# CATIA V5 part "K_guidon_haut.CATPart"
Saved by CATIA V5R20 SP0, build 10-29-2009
Part number: guidon_haut
Publications: "Diametre_guidon_haut", "Longueur_support_poignet"
Bounding box of the stored display mesh (mm): x -250 to 250, y -37.5 to 37.5, z 220 to 707.466
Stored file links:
  G:\Khaled_CFAO_2011\SIL\SIL_GR2\ahabrial\ahabrial\Khaled\CAD_ThinkMOTION\K_guidon_haut.CATPart
  G:\Données\Ecole\IFMA\2A\Thinkmotion2\Etape18\trotinette.CATProduct
  G:\Khaled_CFAO_2011\SIL\SIL_GR2\ahabrial\ahabrial\Etape18\skl_guidon_haut.CATPart
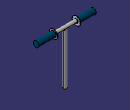
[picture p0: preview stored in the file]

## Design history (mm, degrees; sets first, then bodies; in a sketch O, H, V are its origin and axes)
Parameters
  Diametre_guidon_haut = 30 mm
  Longueur_support_poignet = 500 mm
  Longueur_poignet = 150 mm
  Diametre_poignet = 50 mm
External parameters (linked from other documents)
  External.Longueur_guidon = 300 mm
Set1
  Plane1 "Plan_guidon_haut_poignet": linked copy from another document
  Point1: linked copy from another document
  Plane2 "Plan_ref": linked copy from another document
Body1 (main body)
  Sketch1 on Plane1, origin (0, 0, 670), H (1, 0, 0), V (0, -1, 0)
    circle A1 centre (0, 0) radius 15
    point P1 (0, 0)
    reference projected point E1 (0, 0) from Point1
    radius A1 = 15 {= Diametre_guidon_haut /2}
    coincidence: P1 H, P1 E1
  Pad1: profile Sketch1, direction (0, 0, -1), length 450 {= External.Longueur_guidon *1.5}
  Sketch2 on Plane2, origin (0, 0, 0), H (0, 1, 0), V (0, 0, 1)
    circle A1 centre (0, 670) radius 15
    point P1 (0, 670)
    reference projected point E1 (0, 670) from Point1
    radius A1 = 15 {= Diametre_guidon_haut /2}
    coincidence: P1 E1
  Pad2: profile Sketch2, direction (1, 0, 0), length 250 {= Longueur_support_poignet/2}, mirrored extent
  Sketch3 on end face of Pad2, origin (250, 0, 0), H (0, 1, 0), V (0, 0, 1)
    circle A1 centre (0, 670) radius 25
    point P1 (0, 670)
    reference projected point E1 (0, 670) from Point1
    radius A1 = 25 {= Diametre_poignet /2}
    coincidence: E1 P1
  Pad3: profile Sketch3, direction (-1, 0, 0), length 150 {= Longueur_poignet}
  Mirror1: of Pad3, about Plane2
  Sketch4 on face of Mirror1, origin (-100, 0, 0), H (0, 1, 0), V (0, 0, 1)
    circle A1 centre (0, 670) radius 37.5
    point P1 (0, 670)
    reference projected circle E1 centre (0, 670) radius 25 from edge [face of Pad3 from Sketch3.A1 | start face of Pad3]
    radius A1 = 37.5
    coincidence: P1 V
    concentricity: E1 A1
  Pad4: profile Sketch4, direction (1, 0, 0), length 3
  Fillet1: radius 2, on end face of Pad4
  Fillet2: radius 1, on start face of Pad4
  Fillet3: radius 5, on face of Mirror1
  Sketch5 on end face of Pad3, origin (100, 0, 0), H (0, -1, 0), V (0, 0, 1)
    circle A1 centre (0, 670) radius 37.5
    point P1 (0, 670)
    reference projected circle E1 centre (0, 670) radius 20 from edge [face of Mirror1 | face of Fillet3]
    radius A1 = 37.5
    coincidence: P1 V
    concentricity: A1 E1
  Pad5: profile Sketch5, direction (-1, 0, 0), length 3
  Fillet4: radius 2, on end face of Pad5
  Fillet5: radius 1, on start face of Pad5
